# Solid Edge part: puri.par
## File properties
Author: Cymax
Template: Normal.par
Last saved by: Cymax
Revision: 13
Application: Solid Edge
Accuracy: 0,990
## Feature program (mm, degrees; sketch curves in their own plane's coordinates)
sketch used by "unnamed Protrusion 1" plane through (0, 0, 0) normal (0, -1, 0) x-axis (1, 0, 0)
extrude "unnamed Protrusion 1" add finite 25 symmetric
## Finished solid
Body 1: solid body, 5 faces, 9 edges, 6 vertices.
  Faces by surface: plane 5
  Edges by curve: line 9
Bounding box of the edges (mm): 2898.664 x 25.000 x 6295.977, from (204.8747, -12.5, -2026.9769) to (3103.5382, 12.5, 4269).
Planar faces by outward normal: +y 1, -x 1, -y 1, -z 1, oblique 1
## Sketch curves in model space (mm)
line (204.8747, 0, -2026.9769) -> (204.8747, 0, 4269)
line (204.8747, 0, 4269) -> (3103.5382, 0, -2026.9769)
line (3103.5382, 0, -2026.9769) -> (204.8747, 0, -2026.9769)
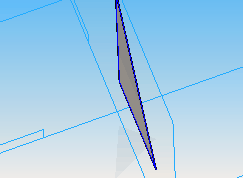
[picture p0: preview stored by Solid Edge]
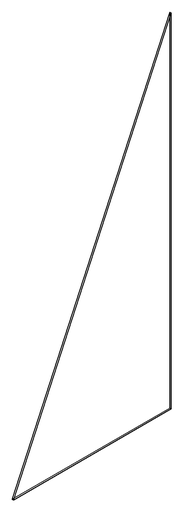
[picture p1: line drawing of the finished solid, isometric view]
